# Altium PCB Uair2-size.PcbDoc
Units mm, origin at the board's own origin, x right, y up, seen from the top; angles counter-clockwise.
Board outline 152.4 x 101.6 mm, 2 copper layers (Top Layer, Bottom Layer); 3 components, 0 nets, 15 pads, 0 vias.
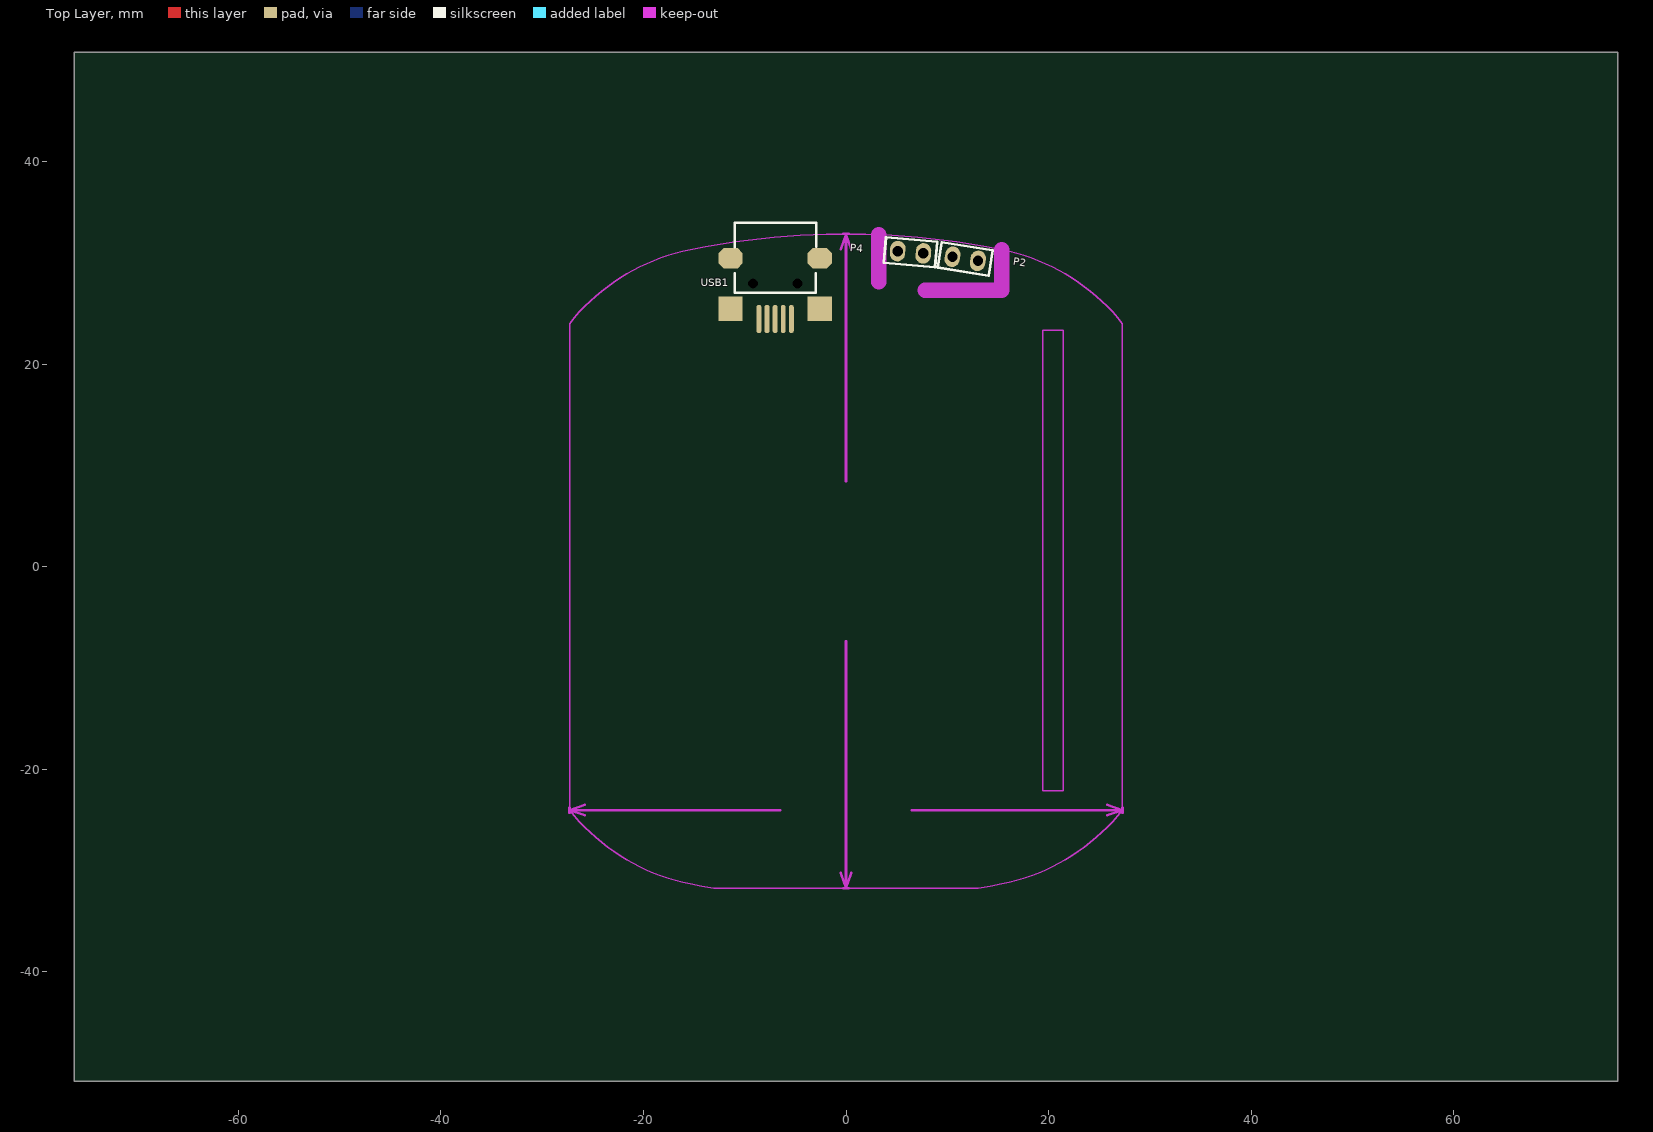
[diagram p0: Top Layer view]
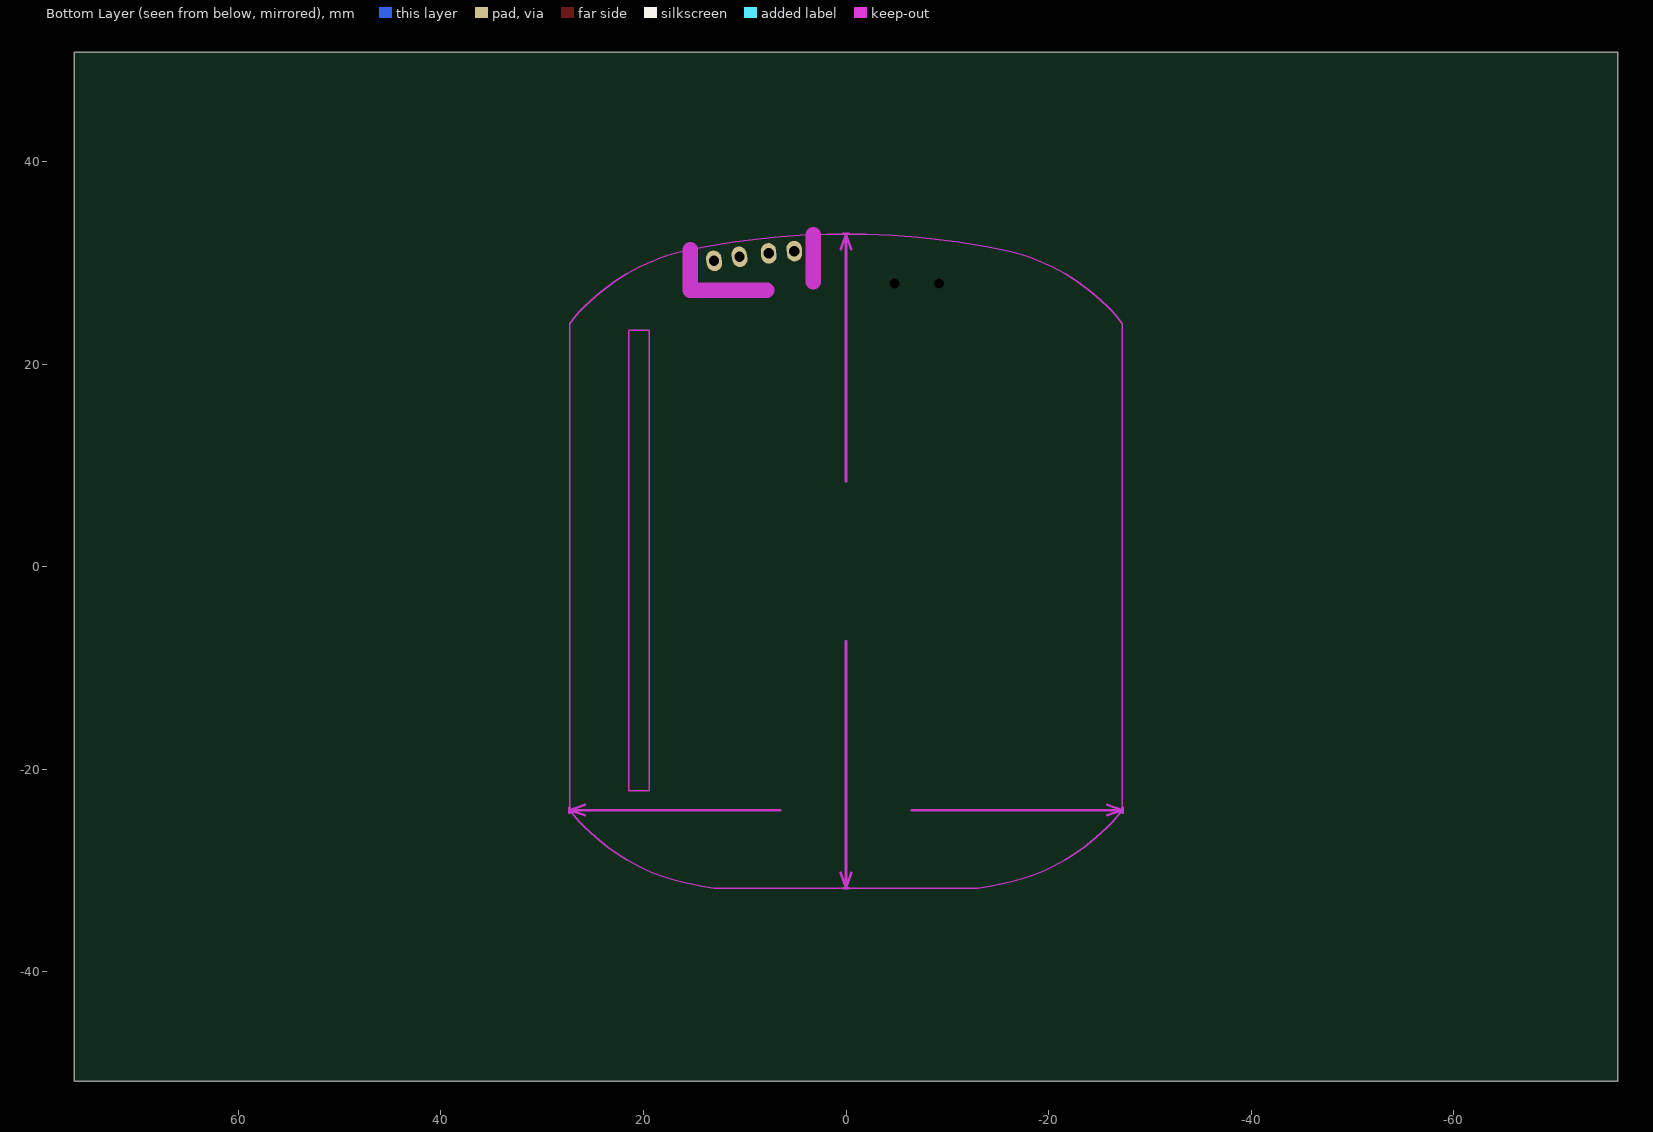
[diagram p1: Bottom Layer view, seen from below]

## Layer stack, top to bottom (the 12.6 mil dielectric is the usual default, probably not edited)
Top Layer: signal copper 0.0356
Dielectric: dielectric 0.32, FR-4, Dk 4.8
Bottom Layer: signal copper 0.0356

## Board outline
-76.2,-50.8 76.2,-50.8 76.2,50.8 -76.2,50.8

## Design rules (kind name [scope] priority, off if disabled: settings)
Clearance [All] p1: gap=0.254
PolygonConnect [All] p1: connectstyle=Relief reliefconductorwidth=0.254 reliefentries=4 polygonreliefangle="90 Angle" airgapwidth=0.254
RoutingVias [All] p1: holewidth=0.711 width=1.27 viastyle="Through Hole" minholewidth=0.711 minwidth=1.27 maxholewidth=0.711 maxwidth=1.27
SolderMaskExpansion [All] p1: expansion=0.102
Width [All] p1: maxlimit=0.254 minlimit=0.254 preferedwidth=0.254
28 further rules are at their usual default settings.

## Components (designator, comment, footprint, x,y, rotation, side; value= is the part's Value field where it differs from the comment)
P2 "HGL12" MF52 10.516,30.607 r351 top
P4 "MF52A1203F3950" MF52 5.105,31.166 r355 top
USB1 "MINIUSB" USB_MINI -7,24.466 r0 top locked

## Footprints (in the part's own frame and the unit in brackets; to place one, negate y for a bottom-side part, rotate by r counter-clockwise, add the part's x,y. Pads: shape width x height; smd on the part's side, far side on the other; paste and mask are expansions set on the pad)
MF52 [mil]
  oval 60x80 hole 40: 1(0,0) 2(100,0)
  silkscreen extent -50,-50 150,50
USB_MINI [mm]
  oval 0.483x2.8 smd: 1(1.6,0) 2(0.8,0) 3(0,0) 4(-0.8,0) 5(-1.6,0)
  rect 2.4x2.4 smd: 6(-4.4,1) 7(4.4,1)
  oct 2.4x2 smd: 8(4.4,6) 9(-4.4,6)
  round 0 hole 1: 10(-2.2,3.5) 11(2.2,3.5)
  silkscreen extent -4,2.6 4.06,9.52

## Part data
P2: library part "Header 2", "Header, 2-Pin"
P4: library part CON2

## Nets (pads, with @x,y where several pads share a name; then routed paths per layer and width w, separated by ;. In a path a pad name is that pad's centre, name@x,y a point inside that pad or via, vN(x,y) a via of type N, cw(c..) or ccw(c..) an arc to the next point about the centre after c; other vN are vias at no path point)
pads on no net: P2.1 P2.2 P4.1 P4.2 USB1.1 USB1.2 USB1.3 USB1.4 USB1.5 USB1.6 USB1.7 USB1.8 USB1.9 USB1.10 USB1.11

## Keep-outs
Keep-Out Layer:
  lines w0.127: -13.05,-31.751 cw(c0,44.997) -15.388,-31.317 cw(c-11.366,-11.368) -27.3,-24.026 -27.3,24.021 cw(c-11.366,11.363) -15.388,31.311 cw(c0,-45.003) -10.95,32.073 cw(c0,-45.003) -3.251,32.78 cw(c0,-45.003) 3.251,32.78 cw(c0,-45.003) 10.95,32.073 cw(c0,-45.003) 15.388,31.312 cw(c11.366,11.363) 27.3,24.021 ; 13.05,-31.751 ccw(c0,44.997) 15.388,-31.317 ccw(c11.366,-11.368) 27.3,-24.026 ; 27.3,-24.026 27.3,24.021 ; 27.3,-24.026 27.3,24.021 ; -13.05,-31.75 13.05,-31.75 -13.05,-31.75 ; 19.431,-22.098 21.463,-22.098 21.463,23.368 19.431,23.368 19.431,-22.098
  lines w0.254: -27.3,-24.28 -27.3,-23.772 ; -25.776,-24.534 -27.3,-24.026 ; -25.776,-23.518 -27.3,-24.026 ; -6.5,-24.026 -27.3,-24.026 ; -0.508,-30.226 0,-31.75 ; -0.508,31.344 0,32.868 ; -0.254,-31.75 0.254,-31.75 ; -0.254,32.868 0.254,32.868 ; 0,-7.338 0,-31.75 ; 0,8.456 0,32.868 ; 0.508,-30.226 0,-31.75 ; 0.508,31.344 0,32.868 ; 6.5,-24.026 27.3,-24.026 ; 25.776,-24.534 27.3,-24.026 ; 25.776,-23.518 27.3,-24.026 ; 27.3,-24.28 27.3,-23.772
  lines w1.524: 3.251,28.118 3.251,32.78 ; 7.798,27.305 15.388,27.305 15.388,31.311
  text "64.618 (mm)" at -0.914,8.202 h1.52 r270
  text "54.6 (mm)" at -6.246,-24.94 h1.52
